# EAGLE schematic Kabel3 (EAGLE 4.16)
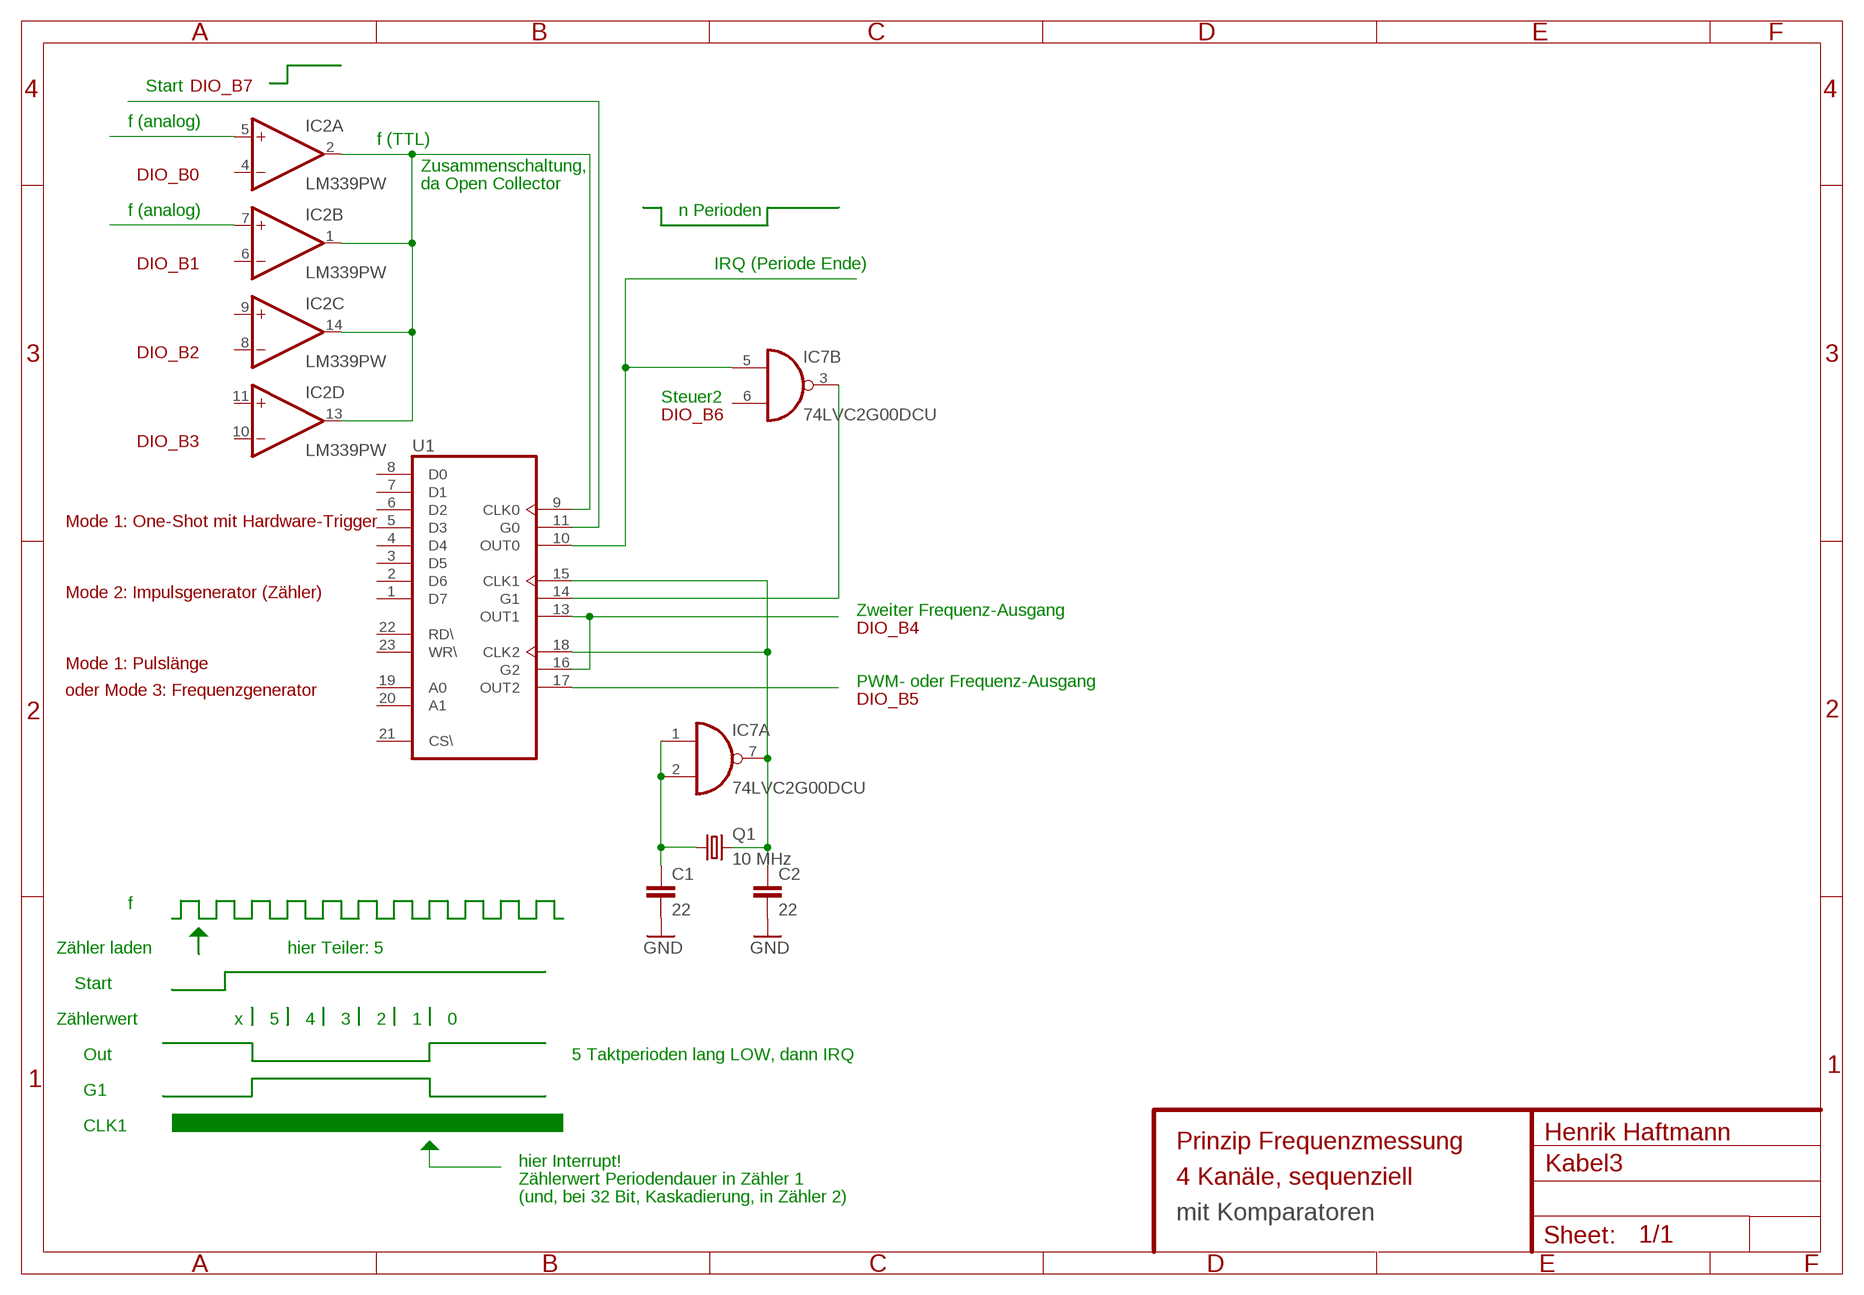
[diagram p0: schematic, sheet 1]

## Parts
C1  22  C-EU025-024X044  [C025-024X044]
C2  22  C-EU025-024X044  [C025-024X044]
IC2  LM339PW  [S14]
IC7  74LVC2G00DCU  [DCU08]
Q1  10 MHz  CRYSTALHC49U-V  [HC49U-V]
U1  82C54  [DIL24-6]

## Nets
K35: C1.2 C2.2 ; supply symbol labelled GND
N$1: C1.1 IC7.1(A:I0) IC7.2(A:I1) Q1.1
N$2: C2.1 IC7.7(A:O) Q1.2 U1.15(CLK1) U1.18(CLK2)
N$3: IC2.5(A:+IN) IC2.7(B:+IN)
N$4: IC7.3(B:O) U1.14(G1)
N$5: IC2.1(B:OUT) IC2.2(A:OUT) IC2.13(D:OUT) IC2.14(C:OUT) U1.9(CLK0)
N$6: U1.13(OUT1) U1.16(G2)
N$7: U1.17(OUT2)
N$8: IC7.5(B:I0) U1.10(OUT0)
STEUERLEITUNG!: U1.11(G0)
Unconnected: IC2.4(A:-IN) IC2.6(B:-IN) IC2.8(C:-IN) IC2.9(C:+IN) IC2.10(D:-IN) IC2.11(D:+IN) IC7.6(B:I1) U1.1(D7) U1.2(D6) U1.3(D5) U1.4(D4) U1.5(D3) U1.6(D2) U1.7(D1) U1.8(D0) U1.19(A0) U1.20(A1) U1.21(CS\) U1.22(RD\) U1.23(WR\)

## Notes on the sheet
- Start | DIO_B7
- f (analog)
- f (TTL)
- Zusammenschaltung,
- DIO_B0
- da Open Collector
- f (analog) | n Perioden
- DIO_B1 | IRQ (Periode Ende)
- DIO_B2
- Steuer2
- DIO_B6
- DIO_B3
- Mode 1: One-Shot mit Hardware-Trigger
- Mode 2: Impulsgenerator (Zähler)
- Zweiter Frequenz-Ausgang
- DIO_B4
- Mode 1: Pulslänge
- PWM- oder Frequenz-Ausgang
- oder Mode 3: Frequenzgenerator
- DIO_B5
- f
- Zähler laden | hier Teiler: 5
- Start
- Zählerwert | x | 5 | 4 | 3 | 2 | 1 | 0
- Out | 5 Taktperioden lang LOW, dann IRQ
- G1
- CLK1
- Henrik Haftmann
- Prinzip Frequenzmessung
- hier Interrupt!
- Zählerwert Periodendauer in Zähler 1 | 4 Kanäle, sequenziell
- (und, bei 32 Bit, Kaskadierung, in Zähler 2)
- mit Komparatoren

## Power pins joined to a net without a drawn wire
GND: IC2.12(P:GND) IC7.4(P:GND) U1.12(GND)
V+: IC2.3(P:V+)
VCC: IC7.8(P:VCC) U1.24(VCC)

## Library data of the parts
C1 C2 = rcl:C-EU: CAPACITOR, European symbol
IC2 = DiffV:LM339: Low Power Low Offset Voltage Quad Comparators with open collector; LM139/LM239/LM339/LM2901/LM3302
IC7 = DiffV:74*2G00: Dual 2-input NAND gate AUC = 3,3 V maximal!
Q1 = crystal:CRYSTAL: CRYSTAL
U1 = micro-harris:82C54: MICROCONTROLLER/MEMORY DEVICE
